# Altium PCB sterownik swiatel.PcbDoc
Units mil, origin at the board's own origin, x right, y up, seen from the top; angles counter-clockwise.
Board outline 6000 x 4000 mil, 2 copper layers (Top Layer, Bottom Layer); 18 components, 32 nets, 108 pads, 7 vias.
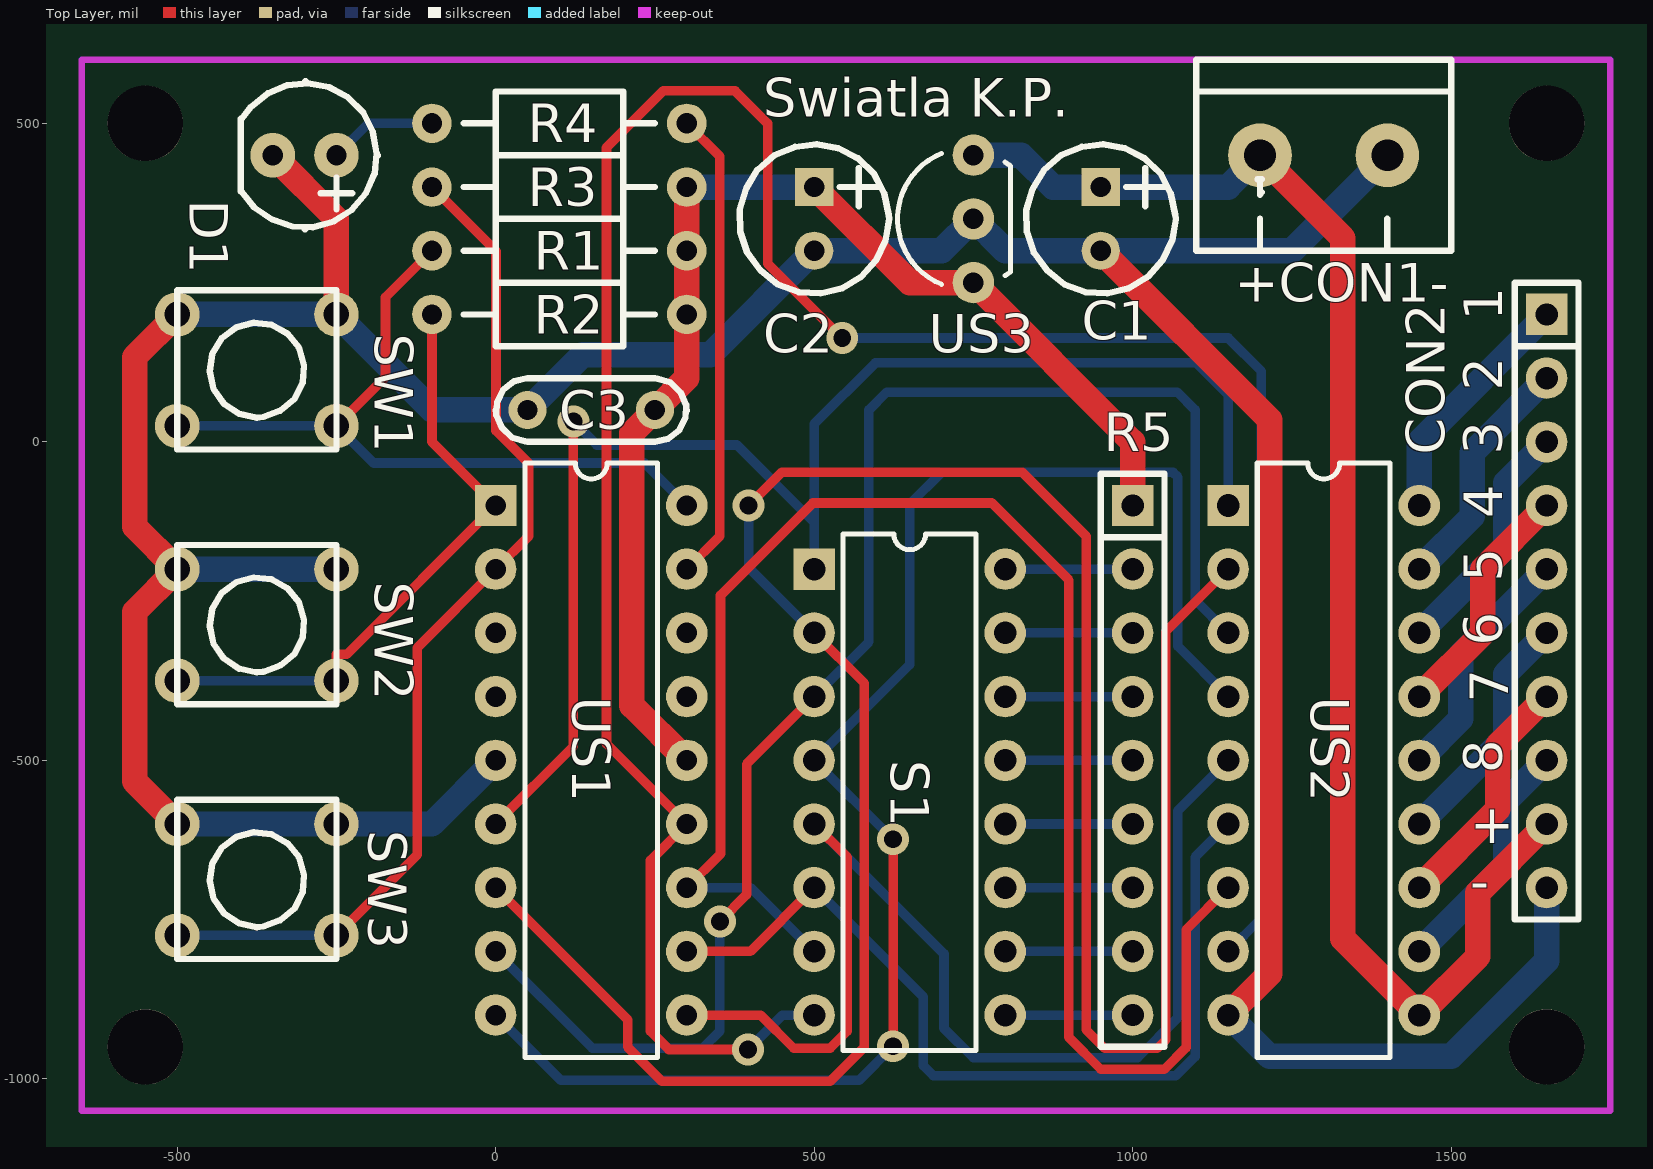
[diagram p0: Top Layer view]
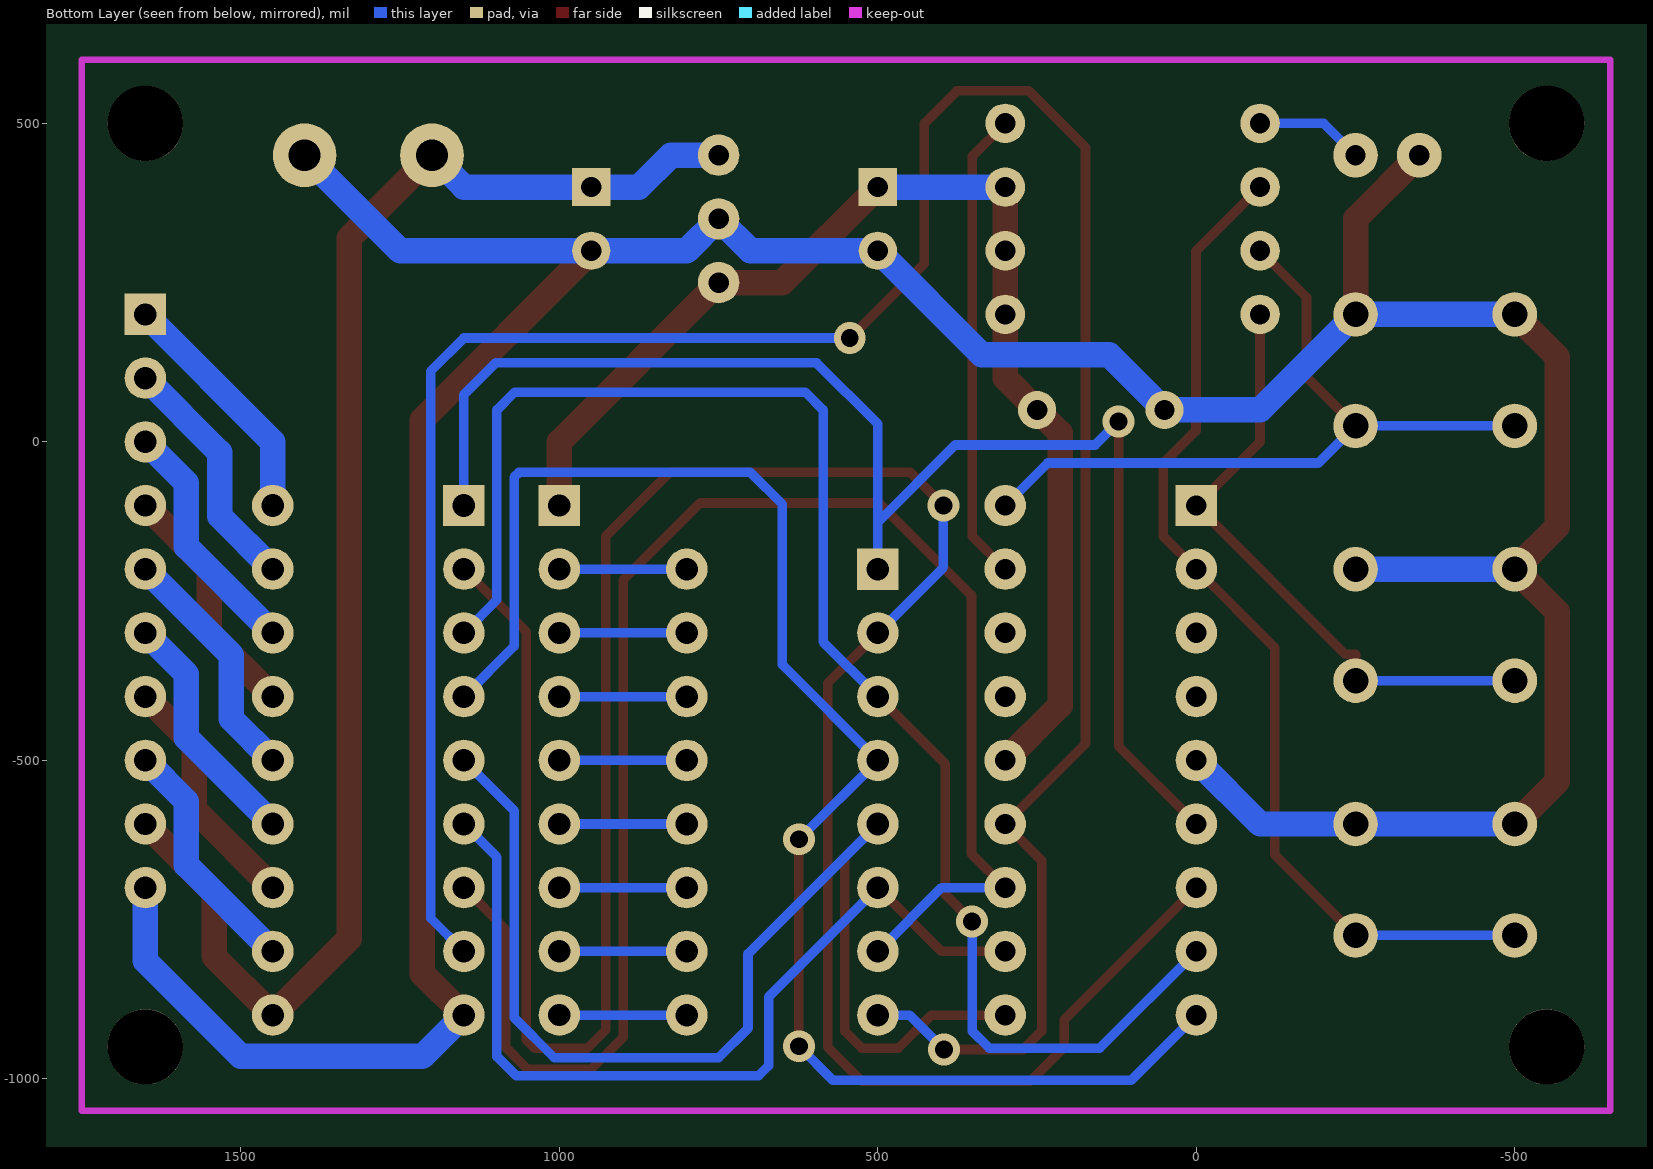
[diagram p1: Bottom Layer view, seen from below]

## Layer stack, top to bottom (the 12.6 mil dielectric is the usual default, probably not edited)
Top Layer: signal copper 1.4
Dielectric: dielectric 12.6, FR-4, Dk 4.8
Bottom Layer: signal copper 1.4

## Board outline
-3350,-2500 2650,-2500 2650,1500 -3350,1500

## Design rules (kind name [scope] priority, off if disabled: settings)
Clearance [All] p1: gap=12
ComponentClearance [All] p1: gap=10 collisioncheckmode=0
PolygonConnect [All] p1: connectstyle=Relief reliefconductorwidth=10 reliefentries=4 polygonreliefangle="90 Angle"
RoutingVias [All] p1: holewidth=28 width=50 viastyle="Through Hole" minholewidth=28 minwidth=50 maxholewidth=28 maxwidth=50
SolderMaskExpansion [All] p1: expansion=4
TestPointUsage [All] p1: valid=0 allowmultiple=FALSE
Testpoint [All] p1: side=15 testpointundercomponent=TRUE minsize=40 maxsize=100 preferedsize=60 minholesize=0 maxholesize=40 preferedholesize=32 testpointgrid=1 style=1023 order=1234567890
Width Width_1 [innet('GND') or innet('V+')  or innet('VCC')or innet('NetCON2_8')or innet('NetCON2_7')or innet('NetCON2_6')or innet('NetCON2_5')or innet('netCON2_4')or innet('NetCON2_3')or innet('NetCON2_2')or innet('NetCON2_1')] p1: maxlimit=40 minlimit=10 preferedwidth=40
Width [All] p2: maxlimit=15 minlimit=10 preferedwidth=15
17 further rules are at their usual default settings.

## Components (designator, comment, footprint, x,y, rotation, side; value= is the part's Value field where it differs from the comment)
+CON1- "ARK2(3,5mm)" con2-5 1300,450 r180 top (schematic designator CON1)
C1 "100u" elektr1 950,400 r0 top
C2 "100u" elektr1 500,400 r0 top
C3 "100n" CAP1 150,50 r180 top
CON2 "Header 10" sip10 1650,200 r270 top
D1 "LED 3mm" LED-5 -250,450 r180 top
R1 "" r 100,300 r0 top
R2 "" r 100,200 r0 top (schematic designator r2)
R3 "" r 100,400 r0 top (schematic designator r3)
R4 "330R" r 100,500 r180 top
R5 "RPAC 8x1k" SIP9 1000,-100 r270 top
S1 "SW DIP-8" DIP-16 650,-550 r270 top
SW1 "SW-PB" key1 -500,200 r270 top
SW2 "SW-PB" key1 -500,-200 r270 top
SW3 "SW-PB" key1 -500,-600 r270 top
US1 "PIC16F818" DIP-18#1 150,-500 r270 top
US2 "ULN 2803A" DIP-18#2 1300,-500 r270 top
US3 "LM78L05" TO-92c 750,250 r180 top

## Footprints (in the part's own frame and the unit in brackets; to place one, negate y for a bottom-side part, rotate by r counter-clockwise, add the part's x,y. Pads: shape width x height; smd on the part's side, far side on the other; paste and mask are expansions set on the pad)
CAP1 [mil]
  round 60 hole 32: 1(-100,0) 2(100,0)
  silkscreen extent -150,-50 150,50
con2-5 [mil]
  round 100 hole 50: 1(100,0) 2(-100,0)
  silkscreen extent -200,-150 200,150
DIP-16 [mil]
  rect 65x65 hole 35.43: 1(-350,-150)
  round 65 hole 35.43: 2(-250,-150) 3(-150,-150) 4(-50,-150) 5(50,-150) 6(150,-150) 7(250,-150) 8(350,-150) 9(350,150) 10(250,150) 11(150,150) 12(50,150) 13(-50,150) 14(-150,150) 15(-250,150) 16(-350,150)
  silkscreen extent -406,-104 406,104
DIP-18#1 [mil]
  rect 65x65 hole 32: 1(-400,-150)
  round 65 hole 32: 2(-300,-150) 3(-200,-150) 4(-100,-150) 5(0,-150) 6(100,-150) 7(200,-150) 8(300,-150) 9(400,-150) 10(400,150) 11(300,150) 12(200,150) 13(100,150) 14(0,150) 15(-100,150) 16(-200,150) 17(-300,150) 18(-400,150)
  silkscreen extent -467,-104 467,104
DIP-18#2 [mil]
  rect 65x65 hole 35.43: 1(-400,-150)
  round 65 hole 35.43: 2(-300,-150) 3(-200,-150) 4(-100,-150) 5(0,-150) 6(100,-150) 7(200,-150) 8(300,-150) 9(400,-150) 10(400,150) 11(300,150) 12(200,150) 13(100,150) 14(0,150) 15(-100,150) 16(-200,150) 17(-300,150) 18(-400,150)
  silkscreen extent -467,-104 467,104
elektr1 [mil]
  rect 60x60 hole 32: 1(0,0)
  round 60 hole 32: 2(0,-100)
  silkscreen extent -117,-167 118,67
key1 [mil]
  round 70 hole 40: 1(0,250) 1(0,0) 2(175,250) 2(175,0)
  silkscreen extent -38,0 212,250
LED-5 [mil]
  round 70 hole 32: 1(0,0) 2(100,0)
  silkscreen extent -65,-116 150,116
r [mil]
  round 62 hole 32: 1(-200,0) 2(200,0)
  silkscreen extent -150,-50 150,50
SIP9 [mil]
  rect 65x65 hole 35: 1(0,0)
  round 65 hole 35: 2(100,0) 3(200,0) 4(300,0) 5(400,0) 6(500,0) 7(600,0) 8(700,0) 9(800,0)
  silkscreen extent -50,-50 850,50
sip10 [mil]
  rect 65x65 hole 35: 1(0,0)
  round 65 hole 35: 2(100,0) 3(200,0) 4(300,0) 5(400,0) 6(500,0) 7(600,0) 8(700,0) 9(800,0) 10(900,0)
  silkscreen extent -50,-50 950,50
TO-92c [mil]
  round 65 hole 32: 1(0,0) 2(0,-100) 3(0,-200)
  silkscreen extent -58,-203 119,3

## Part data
+CON1-: library part CON2, "Connector"
C1 C2: library part ELECTRO2, "Electrolytic Capacitor"
C3: library part CAP, "Capacitor"
CON2: "Header, 10-Pin"
D1: library part LED
R1 R2 R3 R4: library part RES2
R5: library part RPAC
S1: "DIP Switch"
SW1 SW2 SW3: "Switch"
US1: library part PIC16F628
US3: library part VOLTREG

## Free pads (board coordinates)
  round 118.11 hole 118.11: 0(-550,500) 1(-550,-950) 2(1650,-950) 3(1650,500)

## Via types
v1: diameter 50, hole 28, Top Layer to Bottom Layer, 7 vias

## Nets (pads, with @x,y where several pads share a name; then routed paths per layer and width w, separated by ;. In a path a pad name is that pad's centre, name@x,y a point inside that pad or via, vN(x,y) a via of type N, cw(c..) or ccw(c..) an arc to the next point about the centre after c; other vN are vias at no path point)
GND: +CON1-.2 C1.2 C2.2 C3.2 CON2.10 D1.2 SW1.1 SW2.1 SW3.1 US1.5 US2.9 US3.2 | length 6203.8
  Top Layer w40: SW3.1@-500,-600 -567,-533 -567,-267 -500,-200 -567,-133 -567,133 SW1.1@-500,200 ; D1.2 -250,350 SW1.1@-250,200 ; C1.2 1215,35 1215,-835 US2.9
  Bottom Layer w40: SW3.1@-500,-600 -250,-600 -100,-600 US1.5 ; SW2.1@-500,-200 SW2.1@-250,-200 ; SW1.1@-500,200 -250,200 -100,50 C3.2 137,137 337,137 C2.2 700,300 US3.2 800,300 C1.2 1250,300 +CON1-.2 ; US2.9 1215,-965 1500,-965 1650,-815 CON2.10
NetCON2_1: CON2.1 US2.18 | length 382.8
  Bottom Layer w40: US2.18 1450,0 CON2.1
NetCON2_2: CON2.2 US2.17 | length 382.8
  Bottom Layer w40: US2.17 1533.5,-116.5 1533.5,-16.5 CON2.2
NetCON2_3: CON2.3 US2.16 | length 382.8
  Bottom Layer w40: US2.16 1585.5,-164.5 1585.5,-64.5 CON2.3
NetCON2_4: CON2.4 US2.15 | length 382.8
  Top Layer w40: US2.15 1550,-300 1550,-200 CON2.4
NetCON2_5: CON2.5 US2.14 | length 382.8
  Bottom Layer w40: US2.14 1515,-435 1515,-335 CON2.5
NetCON2_6: CON2.6 US2.13 | length 382.8
  Bottom Layer w40: US2.13 1585.5,-464.5 1585.5,-364.5 CON2.6
NetCON2_7: CON2.7 US2.12 | length 382.8
  Top Layer w40: US2.12 1573,-577 1573,-477 CON2.7
NetCON2_8: CON2.8 US2.11 | length 382.8
  Bottom Layer w40: US2.11 1585.5,-664.5 1585.5,-564.5 CON2.8
NetD1_A: D1.1 R4.2 | length 170.7
  Bottom Layer w15: D1.1 -200,500 R4.2
NetR1_1: R1.1 SW1.2 US1.18 | length 1188.9
  Top Layer w15: SW1.2@-250,25 -173,102 -173,227 R1.1
  Bottom Layer w15: SW1.2@-500,25 -250,25 -191.73,-33.27 233.27,-33.27 US1.18
Netr2_1: R2.1 SW2.2 US1.1 | length 979.6
  Top Layer w15: SW2.2@-250,-375 -250,-333.5 -233.5,-333.5 US1.1 -100,0 R2.1
  Bottom Layer w15: SW2.2@-500,-375 SW2.2@-250,-375
Netr3_1: R3.1 SW3.2 US1.2 | length 1613.1
  Top Layer w15: SW3.2@-250,-775 -123,-648 -123,-323 US1.2 52,-148 52,-34 0.5,17.5 0.5,299.5 R3.1
  Bottom Layer w15: SW3.2@-500,-775 SW3.2@-250,-775
NetR4_1: R4.1 US1.17 | length 743.1
  Top Layer w15: US1.17 352,-148 352,448 R4.1
NetR5_2: R5.2 S1.16 | length 200
  Bottom Layer w15: S1.16 R5.2
NetR5_3: R5.3 S1.15 | length 200
  Bottom Layer w15: S1.15 R5.3
NetR5_4: R5.4 S1.14 | length 200
  Bottom Layer w15: S1.14 R5.4
NetR5_5: R5.5 S1.13 | length 200
  Bottom Layer w15: S1.13 R5.5
NetR5_6: R5.6 S1.12 | length 200
  Bottom Layer w15: S1.12 R5.6
NetR5_7: R5.7 S1.11 | length 200
  Bottom Layer w15: S1.11 R5.7
NetR5_8: R5.8 S1.10 | length 200
  Bottom Layer w15: S1.10 R5.8
NetR5_9: R5.9 S1.9 | length 200
  Bottom Layer w15: S1.9 R5.9
NetS1_1: S1.1 US1.6 US2.1 | length 2238.5
  Top Layer w15: US1.6 122,-478 v1(122,32)
  Bottom Layer w15: v1(122,32) 159,-5 378.79,-5 500,-126.21 ; S1.1 500,-126.21 ; US2.1 1150,74 1100,124 596,124 500,28 500,-126.21
NetS1_2: S1.2 US1.7 US2.2 | length 3967.8
  Top Layer w15: US1.7 207,-907 207,-950 261,-1004 525,-1004 579,-950 579,-379 S1.2 ; v1(397,-100) 449,-48 827,-48 927,-148 927,-923 956,-952 1039,-952 1052,-939 1052,-298 US2.2
  Bottom Layer w15: v1(397,-100) 397,-197 S1.2
NetS1_3: S1.3 US1.8 US2.3 | length 2404.8
  Top Layer w15: v1(352,-753) 394,-711 394,-506 S1.3
  Bottom Layer w15: US1.8 152,-952 325,-952 352,-925 v1(352,-753) ; S1.3 586,-314 586,50 614,78 1070,78 1098,50 1098,-248 US2.3
NetS1_4: S1.4 US1.9 US2.4 | length 2474.8
  Top Layer w15: v1(624,-949) v1(624,-624)
  Bottom Layer w15: US1.9 102,-1002 571,-1002 v1(624,-949) ; v1(624,-624) S1.4 650,-350 650,-98 700,-48 1063.57,-48 1071,-55.43 1071,-321 US2.4
NetS1_5: S1.5 US1.10 US2.5 | length 1885.6
  Top Layer w15: US1.10 416,-900 468,-952 525,-952 552,-925 552,-652 S1.5
  Bottom Layer w15: S1.5 703.82,-803.82 703.82,-920.82 750,-967 1008,-967 1071,-904 1071,-579 US2.5
NetS1_6: S1.6 US1.11 US2.6 | length 1423.8
  Top Layer w15: US1.11 400,-800 S1.6
  Bottom Layer w15: S1.6 671.58,-871.58 671.58,-979.58 687,-995 1068,-995 1098,-965 1098,-652 US2.6
NetS1_7: S1.7 US1.12 US2.7 | length 2594.7
  Top Layer w15: US1.12 353,-647 353,-241 498,-96 779,-96 900,-217 900,-935 950,-985 1050,-985 1084,-951 1084,-766 US2.7
  Bottom Layer w15: US1.12 400,-700 S1.7
NetS1_8: S1.8 US1.13 US2.8 | length 4062.7
  Top Layer w15: v1(396,-954) 272,-954 243,-925 243,-657 US1.13 174,-474 174,462 263,551 376,551 427,500 427,280 v1(544,163)
  Bottom Layer w15: v1(396,-954) 450,-900 S1.8 ; v1(544,163) 1150,163 1202,111 1202,-748 US2.8
V+: +CON1-.1 C1.1 CON2.9 US2.10 US3.3 | length 2327.8
  Top Layer w40: +CON1-.1 1330,320 1330,-780 US2.10 1541.98,-808.02 1541.98,-708.02 CON2.9
  Bottom Layer w40: US3.3 825,450 875,400 C1.1 1150,400 +CON1-.1
VCC: C2.1 C3.1 R1.2 R2.2 R3.2 R5.1 US1.14 US3.1 | length 1936.9
  Top Layer w40: US1.14 214,-414 214,14 C3.1 300,100 R2.2 R1.2 R3.2 ; C2.1 650,250 US3.1 1000,0 R5.1
  Bottom Layer w40: R3.2 C2.1
pads on no net: US1.3 US1.4 US1.15 US1.16

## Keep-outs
Keep-Out Layer:
  lines w10: -650,-1050 1750,-1050 1750,600 -650,600 -650,-1050

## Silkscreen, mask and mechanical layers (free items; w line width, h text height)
Top Overlay:
  text "Swiatla K.P." at 420,510 h60
  text "1" at 1580,190 h60 r90
  text "2" at 1580,80 h60 r90
  text "3" at 1580,-20 h60 r90
  text "4" at 1580,-120 h60 r90
  text "5" at 1580,-220 h60 r90
  text "6" at 1580,-320 h60 r90
  text "7" at 1590,-410 h60 r90
  text "8" at 1580,-520 h60 r90
  text "+" at 1530,-630 h60
  text "-" at 1530,-720 h60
